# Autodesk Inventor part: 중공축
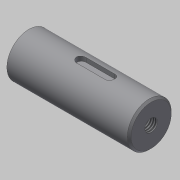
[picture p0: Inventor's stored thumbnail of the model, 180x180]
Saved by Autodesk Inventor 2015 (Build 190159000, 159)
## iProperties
Created: 2019-10
Part Number: 중공축
Material: 강철, 탄소
Document SubType Name: Modeling
Designer: mduedu
Density: 1 g/cm^3
Appearance: 기본값
Author: mduedu
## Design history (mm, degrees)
sketch "스케치1"
  geometry: L1 (0, 0)-(64, 0); L2 (64, 0)-(64, 11.5); L3 (64, 11.5)-(0, 11.5); L4 (0, 11.5)-(0, 0)
  constraints: 8 end point, 2 parallel, 1 horizontal, 1 perpendicular
  dimensions: "d0" = 64 distance of L2.end L3.end; "d2" = 23 diameter of L3 L1
revolve "회전1" sketch "스케치1" stored, may be unused: angle "d3" = 90 deg
hole "구멍1" diameter "d6" = 6.647; stored, may be unused: countersink angle "d10" = 90 deg, drill point angle "d12" = 118 deg; dims "d4" = 10, "d5" = 10, "d7" = 6, "d8" = 4, "d9" = 2, "d11" = 8
hole "구멍2" diameter "d15" = 13; stored, may be unused: countersink angle "d19" = 90 deg, drill point angle "d21" = 0 deg; dims "d13" = 10, "d14" = 10, "d16" = 6, "d17" = 15, "d18" = 20, "d20" = 32
sketch "스케치2"
  geometry: L1 (20, -7.5)-(20, -6.5) reference; L2 (20, -6.5)-(52, -6.5) reference; L3 (52, -6.5)-(52, -3.324) reference; L4 (52, -3.324)-(64, -3.324) reference; L5 (64, -3.324)-(64, -11.5) reference; L6 (64, -11.5)-(0, -11.5) reference; L7 (0, -11.5)-(0, -7.5) reference; L8 (0, -7.5)-(20, -7.5) reference; L9 (20, 6.5)-(20, 7.5) reference; L10 (20, 7.5)-(0, 7.5) reference; L11 (0, 7.5)-(0, 11.5) reference; L12 (0, 11.5)-(64, 11.5) reference; L13 (64, 11.5)-(64, 3.324) reference; L14 (64, 3.324)-(52, 3.324) reference; L15 (52, 3.324)-(52, 6.5) reference; L16 (52, 6.5)-(20, 6.5) reference; L17 (25, 11.5)-(45, 11.5); L18 (45, 11.5)-(45, 9); L19 (45, 9)-(25, 9); L20 (25, 9)-(25, 11.5); 1 further point
  constraints: 8 end point, 2 parallel, 1 horizontal, 1 perpendicular, 1 point on line
  dimensions: "d22" = 20 distance of L17.start L17.end; "d24" = 25 distance between parallel lines of L20 L11; "d25" = 2.5 distance of L17.end L18.end
extrude "돌출1" cut sketch "스케치2" stored distance "d26" = 5; taper "d27" = 0 deg
fillet "모깎기1"
fillet "모깎기2"
sketch "스케치3"
  geometry: 3 further points
  constraints: 2 vertical alignment, 1 other
hole "구멍3" sketch "스케치3" at (0, 7.5) diameter "d28" = 2.459; stored, may be unused: countersink angle "d32" = 90 deg, drill point angle "d34" = 118 deg; dims "d29" = 6, "d30" = 4, "d31" = 2, "d33" = 8
chamfer "모따기1" distance "d35" = 1; stored, may be unused: second distance "d36" = 2, angle "d37" = 45 deg
node "솔리드1"
node "절단 모서리 투영1"
